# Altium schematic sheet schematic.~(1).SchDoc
size A4; SheetNumber: 1; SheetTotal: 1
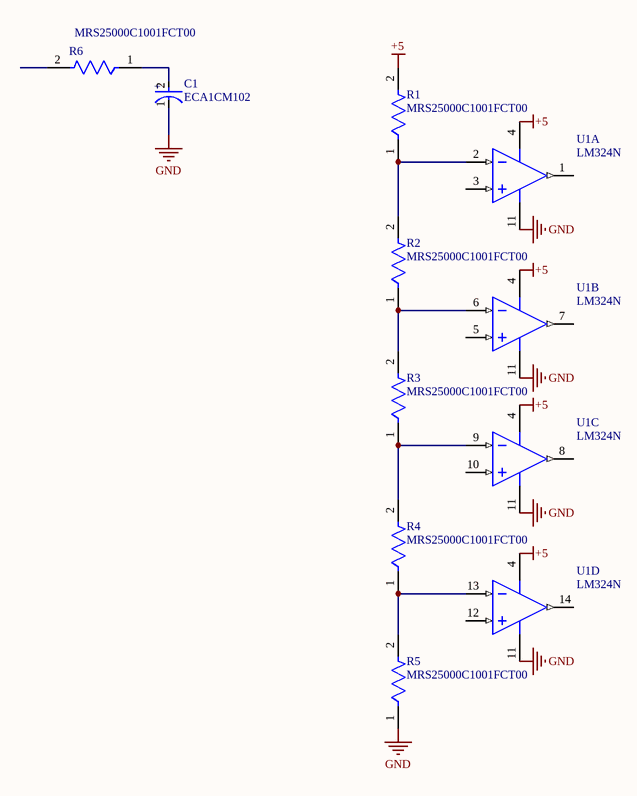
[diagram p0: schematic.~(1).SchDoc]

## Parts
C1  ECA1CM102  [FP-RAD-TH-D_10_0_5-L_16_1-MFG]
R1  MRS25000C1001FCT00  [FP-MRS25-MFG]
R2  MRS25000C1001FCT00  [FP-MRS25-MFG]
R3  MRS25000C1001FCT00  [FP-MRS25-MFG]
R4  MRS25000C1001FCT00  [FP-MRS25-MFG]
R5  MRS25000C1001FCT00  [FP-MRS25-MFG]
R6  MRS25000C1001FCT00  [FP-MRS25-MFG]
U1  LM324N  [N0014A]  (parts A,B,C,D of 4)

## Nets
+5: R1.2 U1.4(V+)
GND: C1.1(C) R5.1 U1.11(GND)
NetC1_2: C1.2(A) R6.1
NetR1_1: R1.1 R2.2 U1.2(IN1-)
NetR2_1: R2.1 R3.2 U1.6(IN2-)
NetR3_1: R3.1 R4.2 U1.9(IN3-)
NetR4_1: R4.1 R5.2 U1.13(IN4-)

Not connected (* = marked no-connect by the designer): R6 2; U1 1(OUT1) 3(IN1+) 5(IN2+) 7(OUT2) 8(OUT3) 10(IN3+) 12(IN4+) 14(OUT4)

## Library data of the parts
C1 = CMP-05427-001524-1: Aluminum Electrolytic Capacitors (Radial Lead Type) 1000uF ±20% 16V; Life (Hours): 2000Hour; Ripple Current (AC): 680mA; Polarity: Polar; Lead/Base Style: Straight; Lead Diameter: 0.6mm; Capacitance: 1mF; Leakage Current: 3uA; Dissipation Factor: 0.2%
R1-R6 = CMP-02408-000051-1: RES 1K OHM 0.6W 1% AXIAL; Power Rating: 600mW; Lead Diameter: 0.6mm; Voltage Rating (DC): 350V; Resistance: 1kR; Temperature Coefficient: 50ppm/°C
U1 = CMP-0055-00082-3: Low Power Quad Operational Amplifier, 14-pin MDIP; Manufacturer: Texas Instruments; CompType: Amplifiers; PowerWise: N; PackageTopMarking: NSUZXYYTTE#*LM324N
